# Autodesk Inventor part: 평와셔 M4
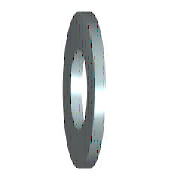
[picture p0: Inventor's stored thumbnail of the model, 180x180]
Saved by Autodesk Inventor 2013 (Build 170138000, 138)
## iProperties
IsCustomPart: 1
Created: 2012-02
Part Number: 평와셔 M4
Material: 스테인리스강
Description: 평면 와셔 - 일반 시리즈 - 제품 등급 A
Document SubType Name: Modeling
Standard: ISO 7089
Designer: mdu-01
Standard Revision: Second edition 2000-06-01
Standards Organization: ISO
Language: ko-KR
Size Designation: 4 - 140 HV
Categories: <MemberInstance><Categories><Category DisplayName="조임쇠" InternalName="e4da775c-781d-43d5-af7c-5136215cf5a6" Mnemonic="FSTN"><Category DisplayName="와셔" InternalN
Density: 8.08 g/cm^3
Author: mdu-01
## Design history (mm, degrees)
sketch "스케치"
  geometry: C1 r 4.5 at (0, 0); C2 r 2.15 at (0, 0); 1 further point
  constraints: 2 centre point, 2 coincident
  dimensions: "d0" = 4.3 diameter of C2 (= SD1); "d1" = 9 diameter of C1 (= SD2)
extrude "본체" new body sketch "스케치" distance "d2" = 0.8 (= SD); taper "d3" = 0 deg
workaxis "Work Axis1"
workplane "Work Plane1"
body "Solid1"
other parameters: "SD1" = 4.3 [user parameter; used in 1 equation term], "SD2" = 9 [user parameter; used in 1 equation term], "SD" = 0.8 [user parameter; used in 1 equation term], "d4" = 0, "d5" = 0, "d6" = 0, "d7" = 0, "NND" = 4 [user parameter]
